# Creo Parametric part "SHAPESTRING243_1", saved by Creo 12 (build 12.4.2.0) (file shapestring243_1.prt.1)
Units: Custom; MM, KILOGRAM, SECS

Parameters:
  PTC_WM_ITERATION = "0"
  PTC_WM_VERSION = "-.0"
  PTC_WM_LIFECYCLE_STATE = "In Work"
  PTC_WM_LIFECYCLE = "MO_CADDocument"
  PTC_WM_CREATED_BY = "Maximilian Roepper (Z0017RMS: MO)"
  PTC_WM_CREATED_ON = "18-Sep-26 11:36:42 AM"
  PTC_WM_MODIFIED_BY = "Maximilian Roepper (Z0017RMS: MO)"
  PTC_WM_MODIFIED_ON = "18-Sep-26 11:36:46 AM"
  PDMLINKNUMBER = "PDM000071455107"
  PTC_WM_NAME = "shapestring243_1.prt"
  PTC_WM_NUMBER = "PDM000071455107"

Other parameters: WEIGHT, WEIGHT_FACTOR, WEIGHT_ADD, _MASS_TEMP, _DIFF_TEMP, MC_ERRORS, SUPPLIER

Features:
  1. coordinate system
  2. datum plane "PRT_YZ"
  3. datum plane "PRT_XY"
  4. datum plane "PRT_XZ"
  5. coordinate system
  6. datum axis
  7. datum axis
  8. datum axis
  9. coordinate system
  10. imported feature
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
Other named items: PRT, SIEMENS_MO, DRW_VIEW_ORG, PRT_X, PRT_Y, PRT_Z, CS0, ROUGH_GROB

Layers: 00_STD_CSYS-KSYS, 01_STD_PLANES-EBENEN, 02_STD_AXES-ACHSEN, 03_STD_CSYS-KSYS, 24_IMPORT_FEAT-IMPORT_KE, INTFCLR

Surfaces: 1 plane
